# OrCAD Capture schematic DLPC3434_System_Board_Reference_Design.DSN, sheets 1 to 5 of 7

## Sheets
1 P07: Disclaimer
2 P01: Title Page: rev: A
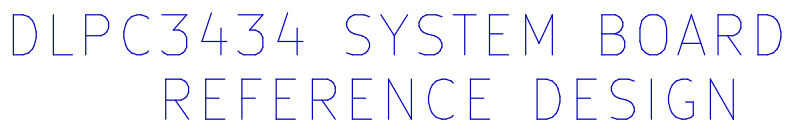
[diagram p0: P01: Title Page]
3 P06: Power Supplies: size D
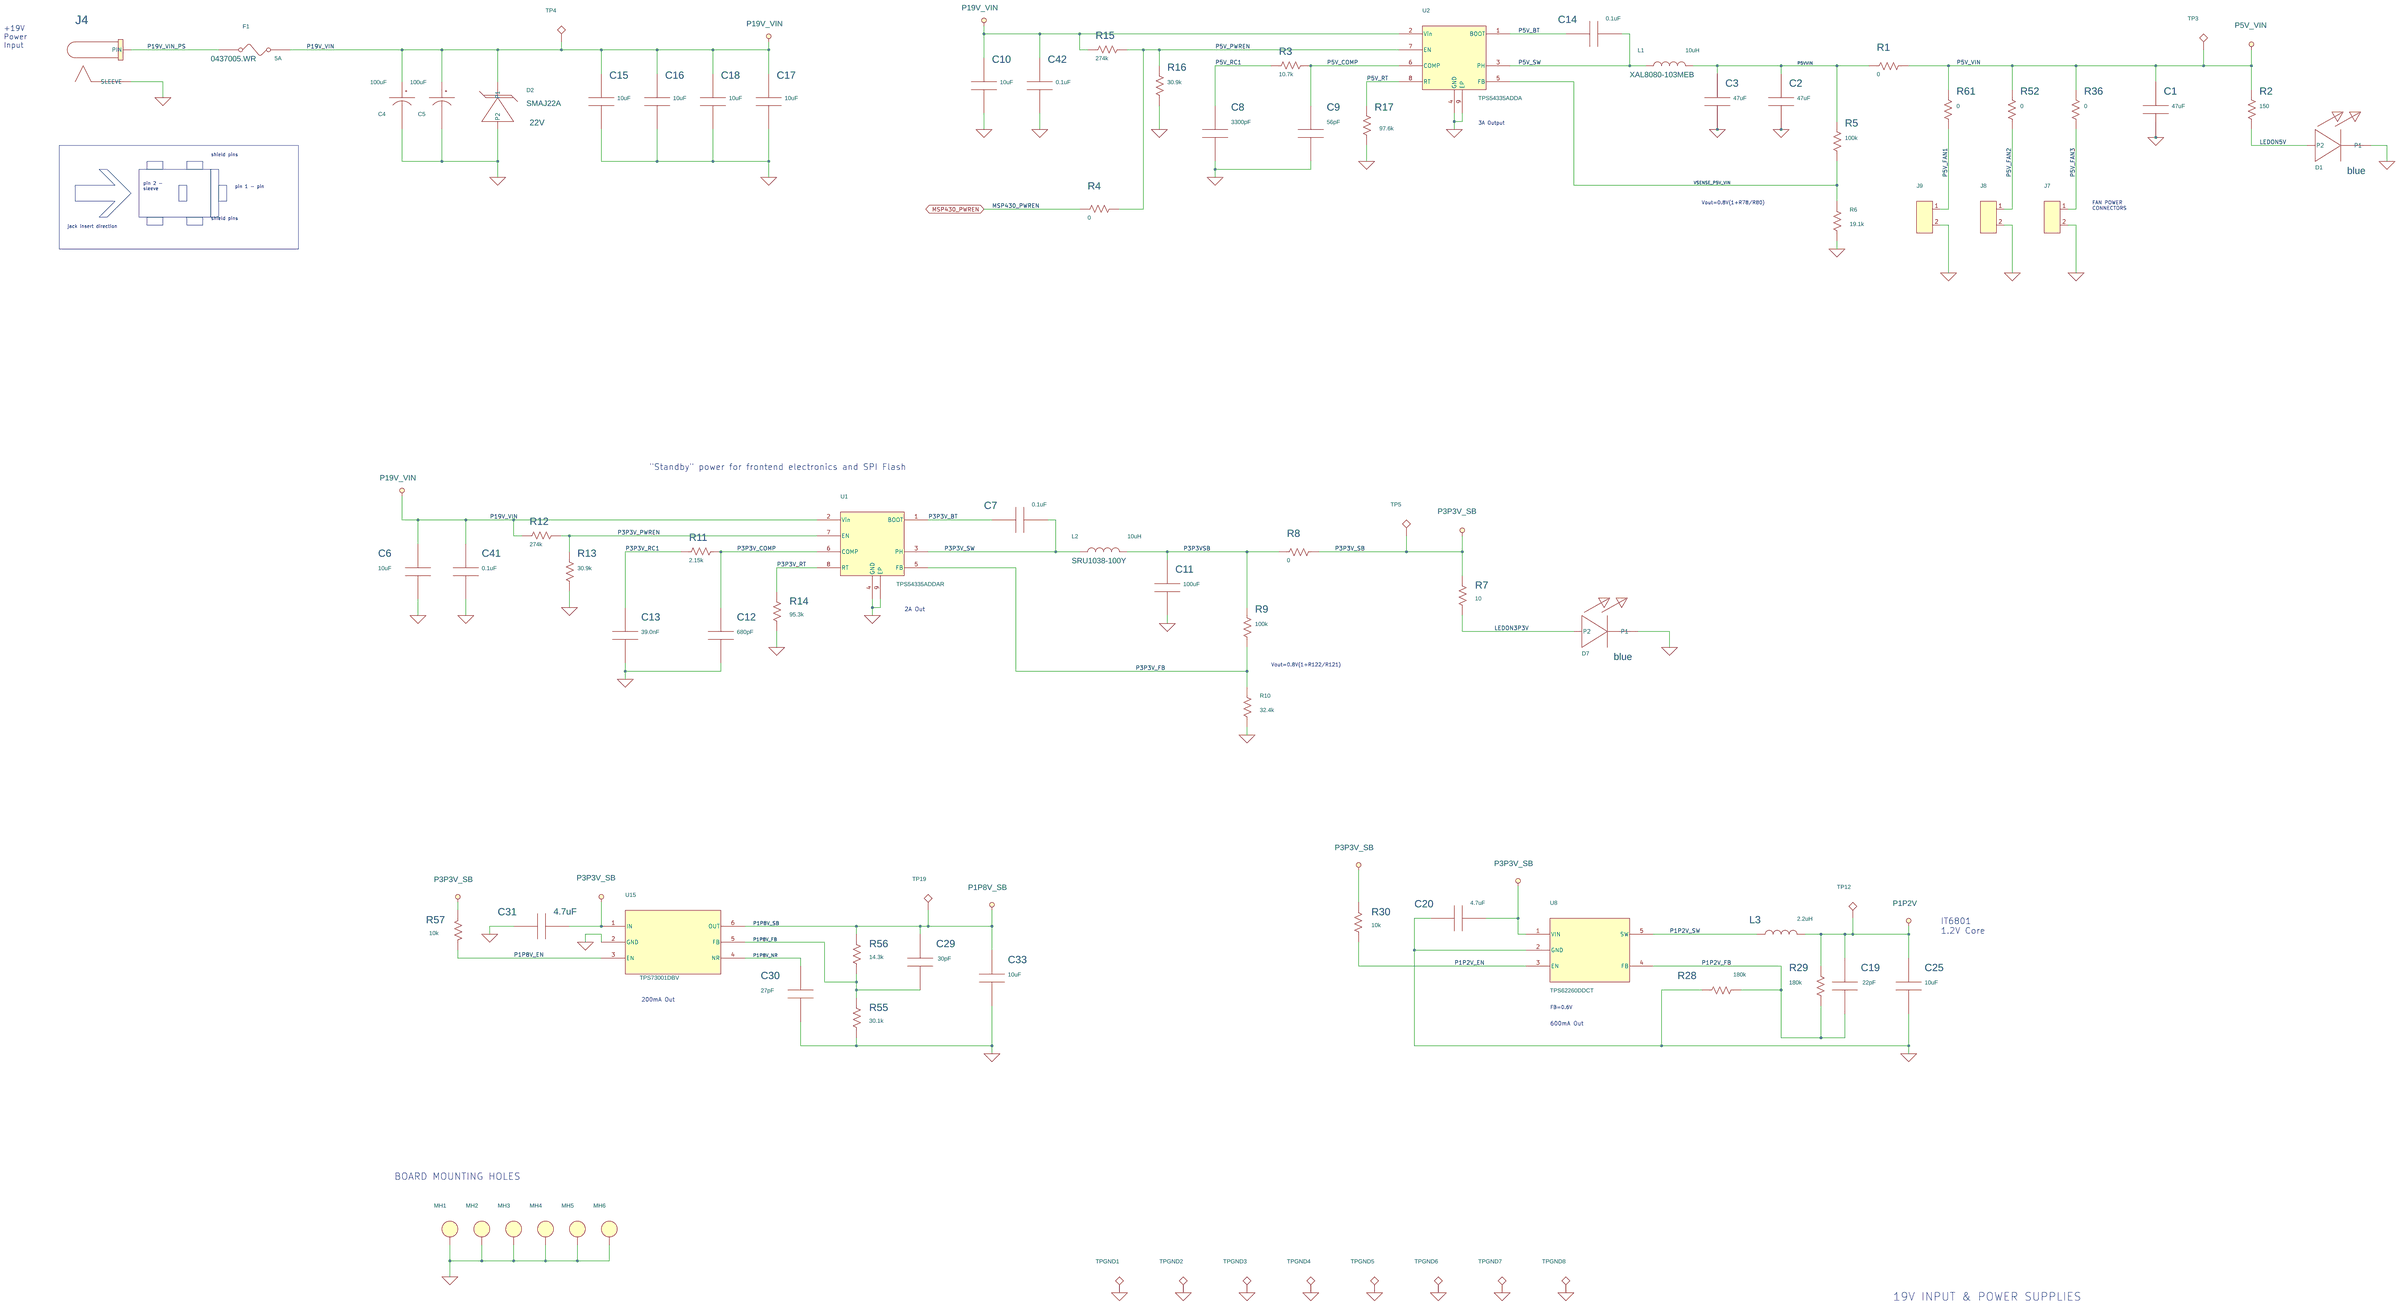
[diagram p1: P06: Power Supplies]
4 P03: IT6801 & HDMI: size D
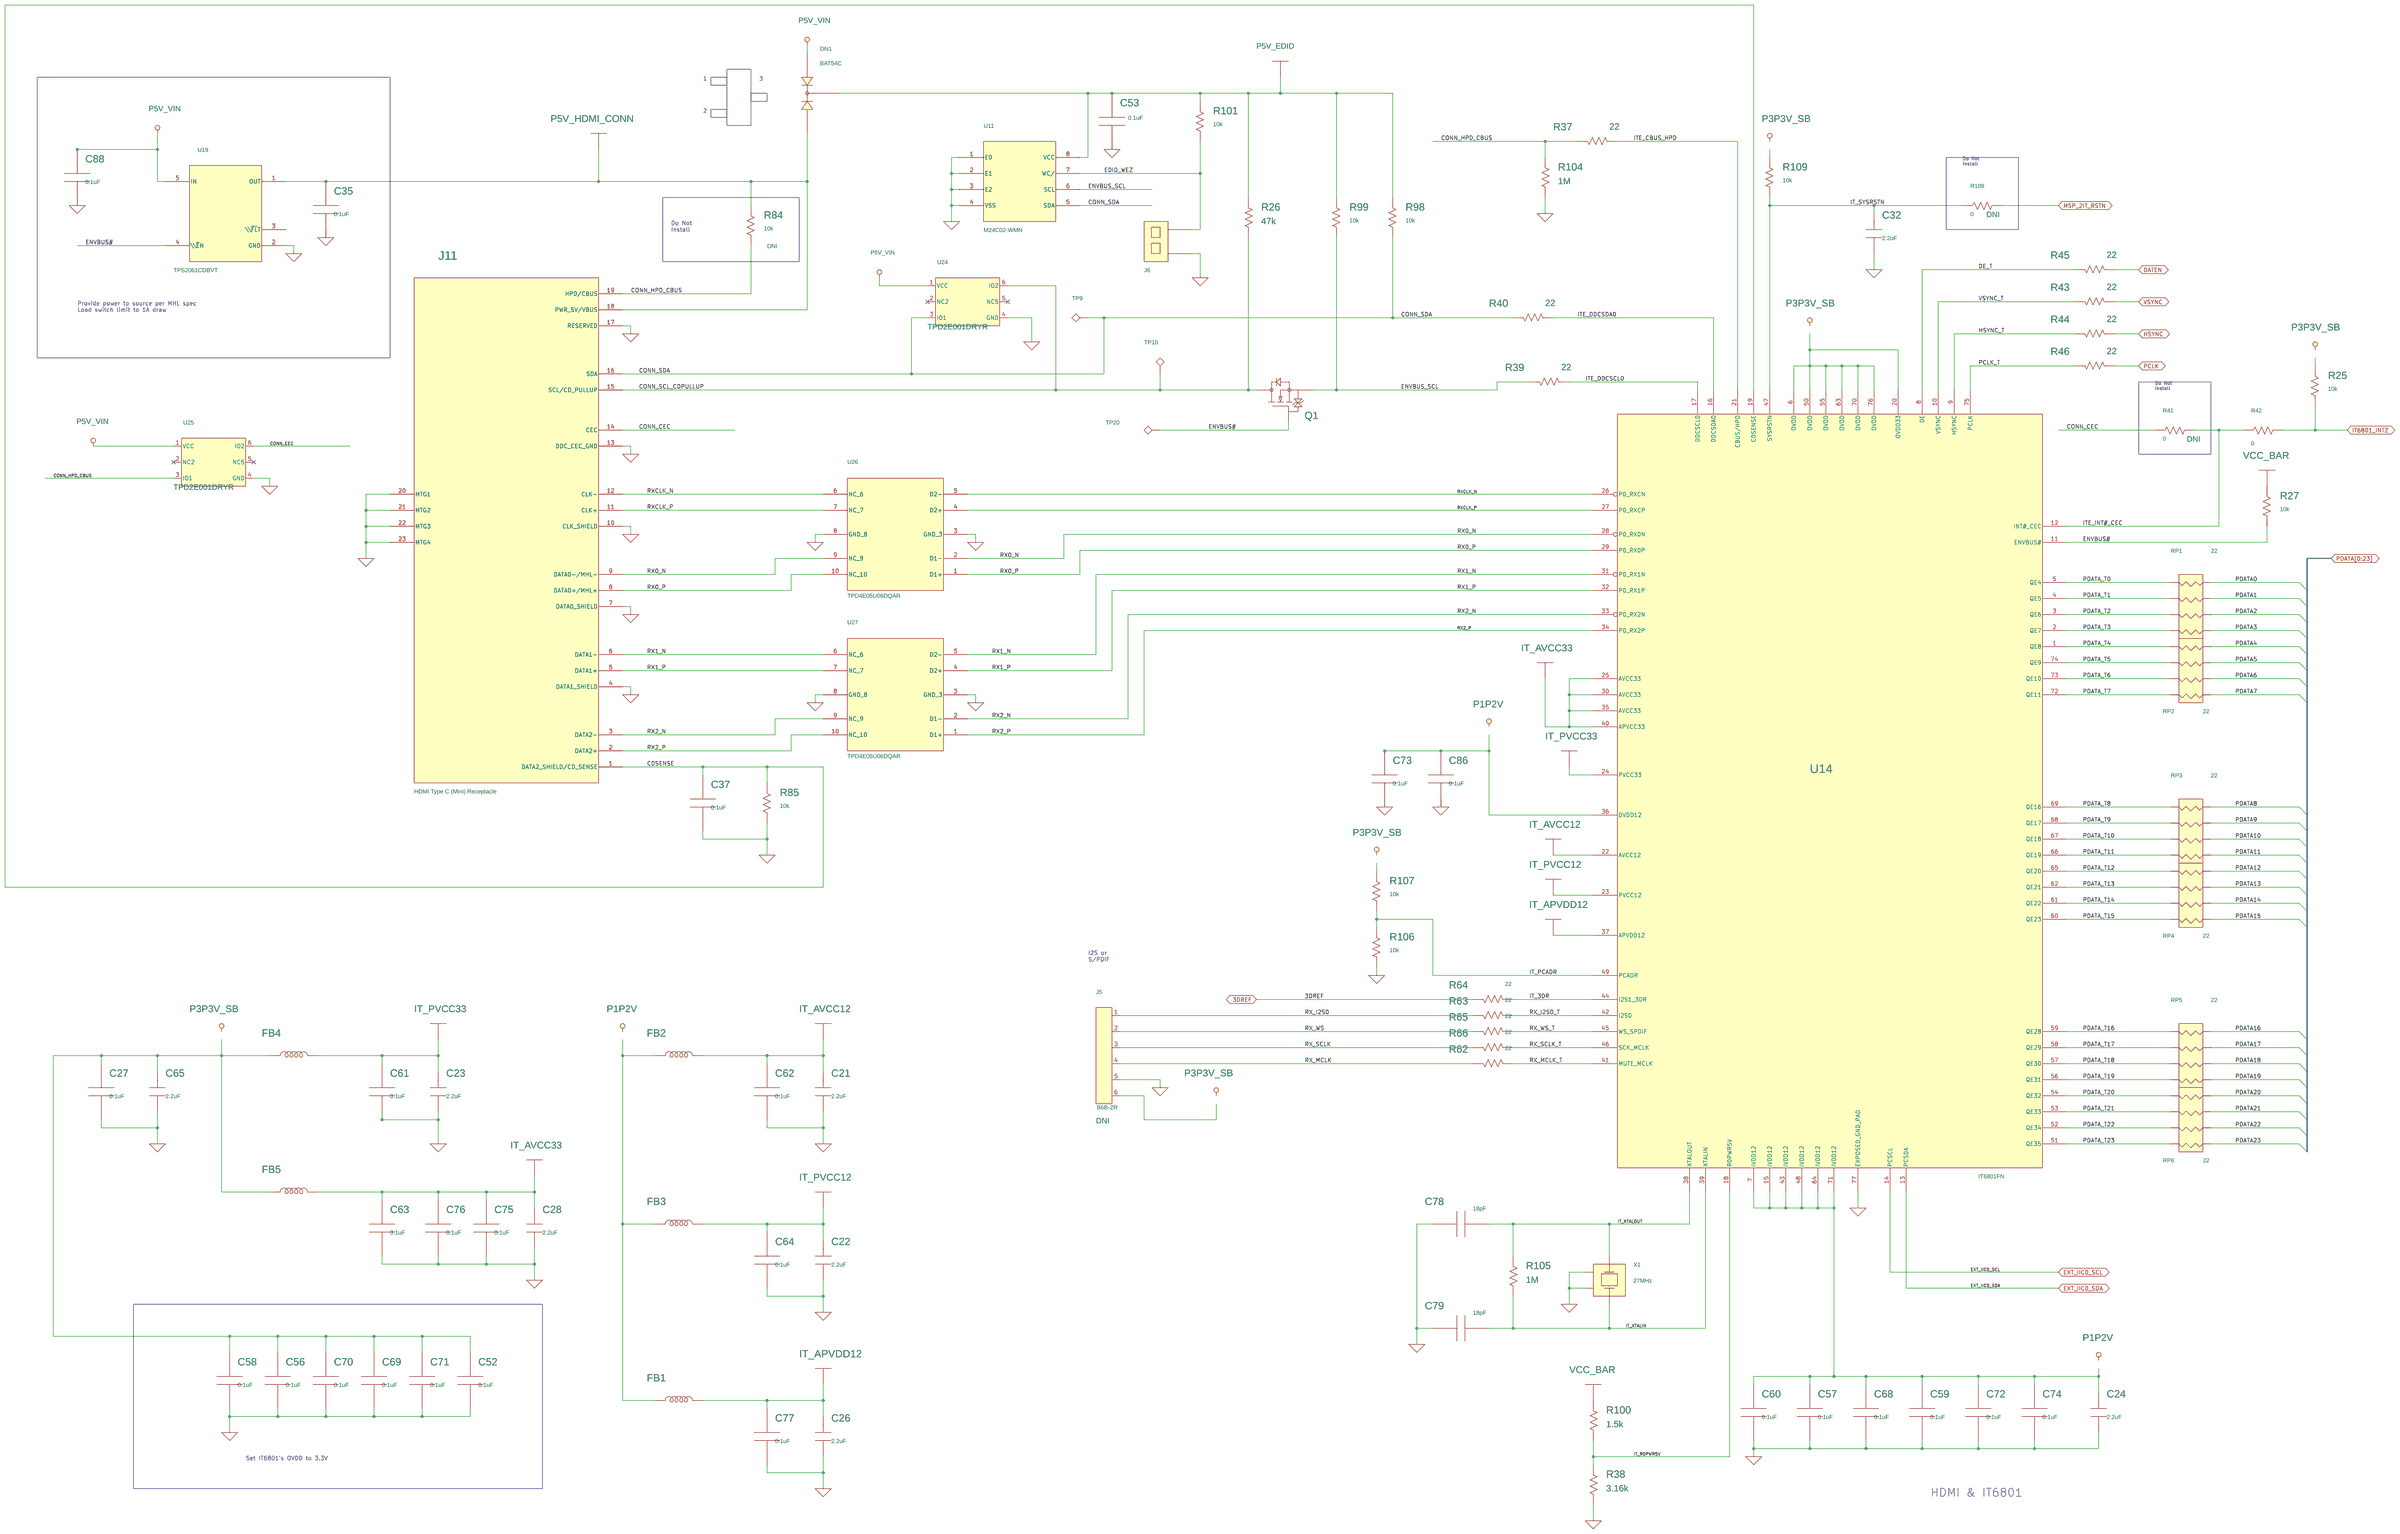
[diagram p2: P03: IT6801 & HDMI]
5 P05: I2C & USB Connections: size D
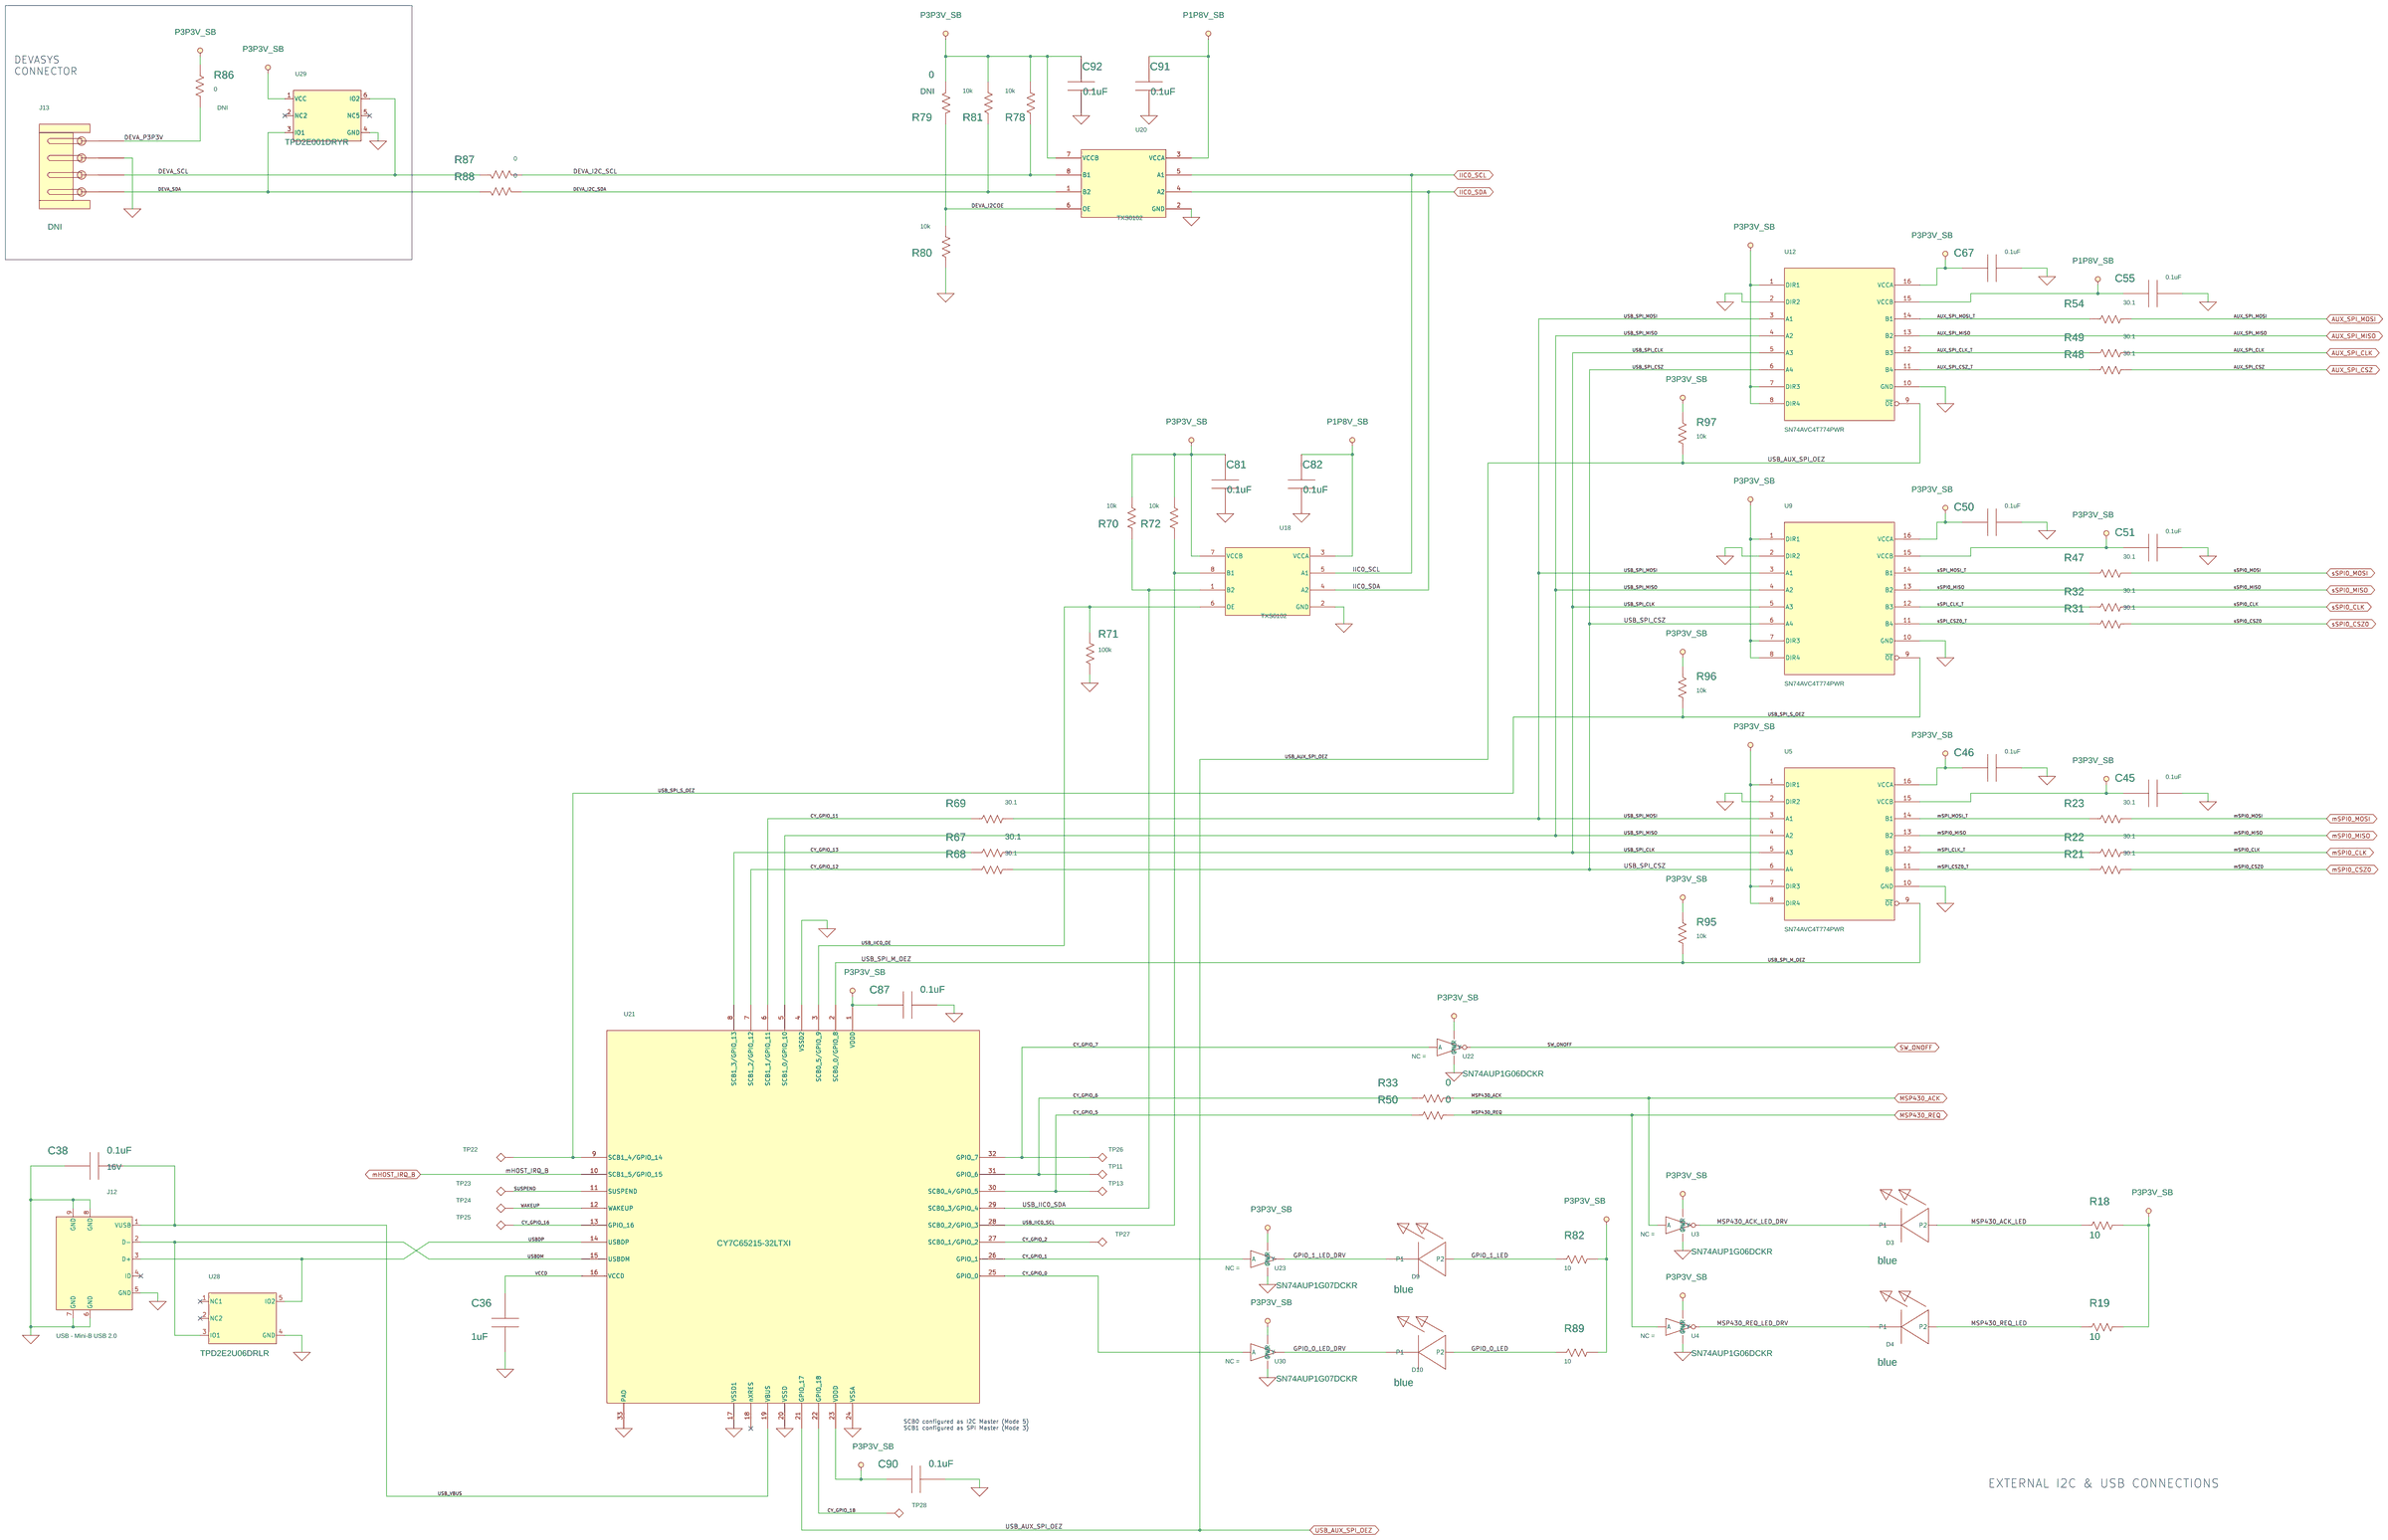
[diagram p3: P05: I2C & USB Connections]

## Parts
sheet P03: IT6801 & HDMI
C21  2.2uF  [0603]
C22  2.2uF  [0603]
C23  2.2uF  [0603]
C24  2.2uF  [0603]
C26  2.2uF  [0603]
C27  0.1uF  [0402]
C28  2.2uF  [0603]
C32  2.2uF  [0603]
C35  0.1uF  [0402]
C37  0.1uF  [0402]
C52  0.1uF  [0402]
C53  0.1uF  [0402]
C56  0.1uF  [0402]
C57  0.1uF  [0402]
C58  0.1uF  [0402]
C59  0.1uF  [0402]
C60  0.1uF  [0402]
C61  0.1uF  [0402]
C62  0.1uF  [0402]
C63  0.1uF  [0402]
C64  0.1uF  [0402]
C65  2.2uF  [0603]
C68  0.1uF  [0402]
C69  0.1uF  [0402]
C70  0.1uF  [0402]
C71  0.1uF  [0402]
C72  0.1uF  [0402]
C73  0.1uF  [0402]
C74  0.1uF  [0402]
C75  0.1uF  [0402]
C76  0.1uF  [0402]
C77  0.1uF  [0402]
C78  18pF  [0402]
C79  18pF  [0402]
C86  0.1uF  [0402]
C88  0.1uF  [0402]
DN1  BAT54C  [SOT-23-3]
FB1  BKP1005EM121-T  [0402]
FB2  BKP1005EM121-T  [0402]
FB3  BKP1005EM121-T  [0402]
FB4  BKP1005EM121-T  [0402]
FB5  BKP1005EM121-T  [0402]
J5  B6B-ZR  [JST_B6B-ZR-SM4-TF_LF_SN_P]
J6  M20-9990245  [HDR2P_1R]
J11  HDMI Type C (Mini) Receptacle  [CNC-2001-1-2-21-00-BK]
Q1  DMN26D0UT-7  [SOT_523]
R25  10k  [0402]
R26  47k  [0402]
R27  10k  [0402]
R37  22  [0402]
R38  3.16k  [0603]
R39  22  [0402]
R40  22  [0402]
R41  0  [0402]
R42  0  [0402]
R43  22  [0402]
R44  22  [0402]
R45  22  [0402]
R46  22  [0402]
R62  22  [0402]
R63  22  [0402]
R64  22  [0402]
R65  22  [0402]
R66  22  [0402]
R84  10k  [0402]
R85  10k  [0402]
R98  10k  [0402]
R99  10k  [0402]
R100  1.5k  [0402]
R101  10k  [0402]
R104  1M  [0402]
R105  1M  [0402]
R106  10k  [0402]
R107  10k  [0402]
R108  0  [0402]
R109  10k  [0402]
RP1  22  [0804]
RP2  22  [0804]
RP3  22  [0804]
RP4  22  [0804]
RP5  22  [0804]
RP6  22  [0804]
TP9  TP,40mil Drill,60mil Pad  [HOLE_PLATED_40mil_DRILL_60mil_PAD]
TP10  TP,40mil Drill,60mil Pad  [HOLE_PLATED_40mil_DRILL_60mil_PAD]
TP20  TP,12mil Drill,32mil Pad  [HOLE_PLATED_12mil_DRILL_32mil_PAD]
U11  M24C02-WMN  [SO8]
U14  IT6801FN  [ITE6801_76pin_QFN]
U19  TPS2061CDBVT  [SOT-753]
U24  TPD2E001DRY  [U_6_DRY]
U25  TPD2E001DRY  [U_6_DRY]
U26  TPD4E05U06DQAR  [10-UFDFN]
U27  TPD4E05U06DQAR  [10-UFDFN]
X1  27MHz  [4SMD]
sheet P05: I2C & USB Connections
C36  1uF  [0402]
C38  0.1uF  [0402_AVXA]
C45  0.1uF  [0402_AVXA]
C46  0.1uF  [0402_AVXA]
C50  0.1uF  [0402_AVXA]
C51  0.1uF  [0402_AVXA]
C55  0.1uF  [0402_AVXA]
C67  0.1uF  [0402_AVXA]
C81  0.1uF  [0402_AVXA]
C82  0.1uF  [0402_AVXA]
C87  0.1uF  [0402_AVXA]
C90  0.1uF  [0402_AVXA]
C91  0.1uF  [0402_AVXA]
C92  0.1uF  [0402_AVXA]
D3  blue  [1206]
D4  blue  [1206]
D9  blue  [1206]
D10  blue  [1206]
J12  USB - Mini-B USB 2.0  [MOLEX_USB_CONN_0513870578]
J13  S4B-EH(LF)(SN)  [CONN4-S4B-EH_JST]
R18  10  [0402]
R19  10  [0402]
R21  30.1  [0402]
R22  30.1  [0402]
R23  30.1  [0402]
R31  30.1  [0402]
R32  30.1  [0402]
R33  0  [0402]
R47  30.1  [0402]
R48  30.1  [0402]
R49  30.1  [0402]
R50  0  [0402]
R54  30.1  [0402]
R67  30.1  [0402]
R68  30.1  [0402]
R69  30.1  [0402]
R70  10k  [0402]
R71  100k  [0402]
R72  10k  [0402]
R78  10k  [0402]
R79  0  [0402]
R80  10k  [0402]
R81  10k  [0402]
R82  10  [0402]
R86  0  [0402]
R87  0  [0402]
R88  0  [0402]
R89  10  [0402]
R95  10k  [0402]
R96  10k  [0402]
R97  10k  [0402]
TP11  TP40  [TP40]
TP13  TP40  [TP40]
TP22  TP40  [TP40]
TP23  TP,12mil Drill,32mil Pad  [HOLE_PLATED_12mil_DRILL_32mil_PAD]
TP24  TP,12mil Drill,32mil Pad  [HOLE_PLATED_12mil_DRILL_32mil_PAD]
TP25  TP,12mil Drill,32mil Pad  [HOLE_PLATED_12mil_DRILL_32mil_PAD]
TP26  TP40  [TP40]
TP27  TP,12mil Drill,32mil Pad  [HOLE_PLATED_12mil_DRILL_32mil_PAD]
TP28  TP,12mil Drill,32mil Pad  [HOLE_PLATED_12mil_DRILL_32mil_PAD]
U3  SN74AUP1G06DCK  [U_5_DCK]
U4  SN74AUP1G06DCK  [U_5_DCK]
U5  SN74AVC4T774PWR  [TSSOP16_PW]
U9  SN74AVC4T774PWR  [TSSOP16_PW]
U12  SN74AVC4T774PWR  [TSSOP16_PW]
U18  TXS0102  [VSSOP-8_DCU]
U20  TXS0102  [VSSOP-8_DCU]
U21  CY7C65215-32LTXI  [CY7C65215_32pin_QFN]
U22  SN74AUP1G06DCK  [U_5_DCK]
U23  SN74AUP1G07DCK  [U_5_DCK]
U28  TPD2E2U06DRL  [SOT-5_DRL_R-PDSO-N5]
U29  TPD2E001DRY  [U_6_DRY]
U30  SN74AUP1G07DCK  [U_5_DCK]
sheet P06: Power Supplies
C1  47uF  [1206]
C2  47uF  [1206]
C3  47uF  [1206]
C4  100uF  [sizeD_260x260mil_radial_can]
C5  100uF  [sizeD_260x260mil_radial_can]
C6  10uF  [1206]
C7  0.1uF  [0402]
C8  3300pF  [0805]
C9  56pF  [0805]
C10  10uF  [1206]
C11  100uF  [1206]
C12  680pF  [0805]
C13  39.0nF  [0402]
C14  0.1uF  [0402]
C15  10uF  [1206]
C16  10uF  [1206]
C17  10uF  [1206]
C18  10uF  [1206]
C19  22pF  [0402]
C20  4.7uF  [0402]
C25  10uF  [0603]
C29  30pF  [0402]
C30  27pF  [0402]
C31  4.7uF  [0402]
C33  10uF  [0603]
C41  0.1uF  [0402]
C42  0.1uF  [0402]
D1  blue  [1206]
D2  SMAJ22A  [SMA]
D7  blue  [1206]
F1  5A  [1206]
J4  PJ-082BH  [CUI_PJ-082BH]
J7  S2B-ZR  [JST_S2B_ZR]
J8  S2B-ZR  [JST_S2B_ZR]
J9  S2B-ZR  [JST_S2B_ZR]
L1  10uH  [Coilcraft_XAL8080]
L2  10uH  [Bourns_SRU1038]
L3  2.2uH  [1008_2p5mmx2mm]
MH1  MOUNTING_HOLE  [MH147-276GND]
MH2  MOUNTING_HOLE  [MH147-276GND]
MH3  MOUNTING_HOLE  [MH147-276GND]
MH4  MOUNTING_HOLE  [MH147-276GND]
MH5  MOUNTING_HOLE  [MH147-276GND]
MH6  MOUNTING_HOLE  [MH147-276GND]
R1  0  [0805]
R2  150  [0402]
R3  10.7k  [0402]
R4  0  [0402]
R5  100k  [0402]
R6  19.1k  [0805]
R7  10  [0402]
R8  0  [0805]
R9  100k  [0402]
R10  32.4k  [0805]
R11  2.15k  [0402]
R12  274k  [0402]
R13  30.9k  [0402]
R14  95.3k  [0402]
R15  274k  [0402]
R16  30.9k  [0402]
R17  97.6k  [0402]
R28  180k  [0402]
R29  180k  [0402]
R30  10k  [0402]
R36  0  [0402]
R52  0  [0402]
R55  30.1k  [0402]
R56  14.3k  [0402]
R57  10k  [0402]
R61  0  [0402]
TP3  TP,40mil Drill,60mil Pad  [HOLE_PLATED_40mil_DRILL_60mil_PAD]
TP4  TP,40mil Drill,60mil Pad  [HOLE_PLATED_40mil_DRILL_60mil_PAD]
TP5  TP,40mil Drill,60mil Pad  [HOLE_PLATED_40mil_DRILL_60mil_PAD]
TP12  TP,40mil Drill,60mil Pad  [HOLE_PLATED_40mil_DRILL_60mil_PAD]
TP19  TP,40mil Drill,60mil Pad  [HOLE_PLATED_40mil_DRILL_60mil_PAD]
TPGND1  TP_BLK  [KEYSTONE_TP_MINIATURE]
TPGND2  TP_BLK  [KEYSTONE_TP_MINIATURE]
TPGND3  TP_BLK  [KEYSTONE_TP_MINIATURE]
TPGND4  TP_BLK  [KEYSTONE_TP_MINIATURE]
TPGND5  TP_BLK  [KEYSTONE_TP_MINIATURE]
TPGND6  TP_BLK  [KEYSTONE_TP_MINIATURE]
TPGND7  TP_BLK  [KEYSTONE_TP_MINIATURE]
TPGND8  TP_BLK  [KEYSTONE_TP_MINIATURE]
U1  TPS54335ADDAR  [8-SO-PWRPAD_DDA_R-PDSO-G8]
U2  TPS54335ADDA  [8-SO-PWRPAD_DDA_R-PDSO-G8]
U8  TPS62260DDCT  [TSOT-23_DDC_R-PDSO-G5]
U15  TPS73001DBV  [SOT23-6_DBV_R-PDSO-G6]

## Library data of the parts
C21-C24 C26 C28 C32 C65 = CER_2.2UF_25V_10%_X5R_0603: DigiKey: 587-2909-1-ND; DigiReel: 587-2909-6-ND; Install: Y; P/D_NUM: TMK107ABJ225KA-T; Part Number: TMK107ABJ225KA-T; Part Specific: 2.2µF 25V Ceramic Capacitor X5R 0603; Type: Capacitor; VPC: 25V; Vendor: Taiyo Yuden
C7 C14 C27 C35 C37 C41 C42 C52 C53 C56-C64 C68-C77 C86 C88 = PAS,CAP,NP,large: DigiKey: 445-6899-1-ND; DigiReel: 445-6899-6-ND; Family: passive; Lead Style: SMT; MFG: TDK; Material: X7R; P/D_NUM: CGA2B3X7R1H104K050BB; Part Number: CGA2B3X7R1H104K050BB; Part Specific: 0.10µF 50V Ceramic Capacitor X7R 0402; TOLERANCE: 10%; Type: capacitor; VENDOR: TDK; VPC: 50V
C78 C79 = PAS,CAP,NP,large: DigiKey: 490-5858-1-ND; DigiReel: 490-5858-6-ND; Family: passive; Lead Style: SMT; MFG: Murata; Material: NP0; P/D_NUM: GRM1555C1H180JA01D; Part Number: GRM1555C1H180JA01D; Part Specific: CAP CER 18PF 50V NP0 5% 0402; TOLERANCE: 5%; Type: capacitor; VENDOR: Murata; VPC: 50V
DN1 = DIODE_DUAL_Schott_Common_Cath: DigiKey: BAT54C-FDICT-ND; DigiReel: BAT54C-FDIDKR-ND; Install: Y; Lead Style: SMT; P/D_NUM: BAT54C-7-F; Part Number: BAT54C-7-F; Part Specific: DIODE ARRAY SCHOTTKY 30V 200mA SOT23-3; Type: Diode; VPC: 30V; Vendor: Diodes Inc.
FB1-FB5 = FERRITE_CHIP_120_OHM_1.5A_0402: DigiKey: 587-3289-1-ND; DigiReel: 587-3289-6-ND; Install: Y; Lead Style: SMT; Part Specific: FERRITE CHIP 80 OHM 1500MA 0402; Type: Ferrite; Vendor: Taiyo Yuden
J5 = EM,HDR,6P,1R,2x: DigiKey: 455-1685-1-ND; DigiReel: 455-1685-6-ND; Family: electro/mechanical; Install: DNI; Lead Style: SMT; MFG: JST; P/D_NUM: B6B-ZR-SM4-TF(LF)(SN)(P); Part Number: B6B-ZR-SM4-TF(LF)(SN)(P); Part Specific: CONN HEADER ZH TOP 6POS 1.5MM; Pin Cnt: 6; Pin Spacing: 1.5mm; Row Cnt: 1; Type: header; Vendor: JST
J6 = 2POS_SMT_HEADER_2_0.54MM: DigiKey: 952-2261-ND; DigiReel: ---; Digikey Part Number: 952-2261-ND; Family: electro/mechanical; Install: Y; Lead Style: TH; Part Specific: CONN HEADER 2 POS 0.1IN SIL VERT; Pin Cnt: 2; Pin Spacing: 100mil; Row Cnt: 1; Type: Header; Vendor: Harwin
J11 = HDMI-Mini_Receptacle_w_MHL: DigiKey: 1175-1704-1-ND; DigiReel: 1175-1704-6-ND; Digikey Part Number: 1175-1704-1-ND; Install: Y; Lead Style: SMT; MFG: CNC Tech; MFG Part Number: 2001-1-2-21-00-BK; P/D_NUM: 2001-1-2-21-00-BK; Part Number: 2001-1-2-21-00-BK; Part Specific: MINI HDMI 19P FEMALE SMT; Pin Cnt: 19; Pin Spacing: 0.4MM; Row Cnt: 1; Type: HDMI - Mini; Vendor: CNC Tech
Q1 = TMP_134732: DigiKey: DMN26D0UT-7DICT-ND; DigiReel: DMN26D0UT-7DIDKR-ND; Part Specific: MOSFET N-CH 20V 230MA SOT523; Type: Mosfet; VPC: 20V; Vendor: Diodes Inc
R25 R27 R30 R57 R70 R72 R78 R81 R85 R95-R99 R101 R106 R107 R109 = PAS,R,large: DigiKey: P10.0KLCT-ND; DigiReel: P10.0KLDKR-ND; Family: passive; Index PN: 680; Lead Style: SMT; MFG: Panasonic; Material: chip; P/D_NUM: ERJ-2RKF1002X; Part Number: ERJ-2RKF1002X; Part Specific: RES SMD 10K OHM 1% 1/10W 0402; Power: 1/16W; TOLERANCE: 1%; Type: resistor; VENDOR: Panasonic; VPC: 1/16W
R26 = PAS,R,large: DigiKey: P47.0KLCT-ND; DigiReel: P47.0KLDKR-ND; Family: passive; Index PN: 1030; Lead Style: SMT; MFG: Panasonic; Material: chip; P/D_NUM: ERJ-2RKF4702X; Part Number: ERJ-2RKF4702X; Part Specific: RES 47.0K OHM 1/10W 1% 0402 SMD; Type: resistor; VPC: 1/16W; Vendor: Panasonic
R37 R39 R40 R43-R46 R62-R66 = PAS,R,large: DigiKey: P22.0LCT-ND; DigiReel: P22.0LDKR-ND; Digikey Part Number: P22.0LCT-ND; Family: passive; Lead Style: SMT; MFG: Panasonic; MFG Part Number: ERJ-2RKF22R0X; Material: chip; P/D_NUM: ERJ-2RKF22R0X; Part Number: ERJ-2RKF22R0X; Part Specific: RES SMD 22 OHM 1% 1/10W 0402; Power: 1/16W; Rating: 1/10W; TOLERANCE: 1%; Type: resistor; VPC: 1/10W; Vendor: Panasonic
R38 = PAS,R,large: DigiKey: P3.16KHCT-ND; DigiReel: P3.16KHDKR-ND; Family: passive; Lead Style: SMT; MFG: Panasonic; Material: chip; P/D_NUM: ERJ-3EKF3161V; Part Number: ERJ-3EKF3161V; Part Specific: RES SMD 3.16K OHM 1% 1/10W 0603; TOLERANCE: 1%; Type: resistor; VENDOR: Panasonic; VPC: 1/10W
R41 R79 R86 R108 = PAS,R,large: DigiKey: P0.0JCT-ND; DigiReel: P0.0JDKR-ND; Family: passive; Index PN: 687; Install: DNI; Lead Style: SMT; MFG: Panasonic; Material: chip; P/D_NUM: ERJ-2GE0R00X; Part Number: ERJ-2GE0R00X; Part Specific: RES 0.0 OHM 1/16W 0402 SMD; Power: 1/16W; Type: resistor; VPC: 1/16W; Vendor: Panasonic
R4 R36 R42 R52 R61 = PAS,R,large: DigiKey: P0.0JCT-ND; DigiReel: P0.0JDKR-ND; Family: passive; Index PN: 687; Install: Y; Lead Style: SMT; MFG: Panasonic; Material: chip; P/D_NUM: ERJ-2GE0R00X; Part Number: ERJ-2GE0R00X; Part Specific: RES 0.0 OHM 1/16W 0402 SMD; Power: 1/16W; Type: resistor; VPC: 1/16W; Vendor: Panasonic
R84 = PAS,R,large: DigiKey: P10.0KLCT-ND; DigiReel: P10.0KLDKR-ND; Family: passive; Index PN: 680; Install: DNI; Lead Style: SMT; MFG: Panasonic; Material: chip; P/D_NUM: ERJ-2RKF1002X; Part Number: ERJ-2RKF1002X; Part Specific: RES SMD 10K OHM 1% 1/10W 0402; Power: 1/16W; TOLERANCE: 1%; Type: resistor; VENDOR: Panasonic; VPC: 1/16W
R100 = PAS,R,large: DigiKey: P1.50KLCT-ND; DigiReel: P1.50KLDKR-ND; Family: passive; Index PN: 1117; Lead Style: SMT; MFG: Panasonic; Material: chip; P/D_NUM: ERJ-2RKF1501X; Part Number: ERJ-2RKF1501X; Part Specific: RES 1.50K OHM 1/10W 1% 0402 SMD; TOLERANCE: 1%; Type: resistor; VENDOR: Panasonic; VPC: 1/10W
R104 R105 = PAS,R,large: DigiKey: P1.00MLCT-ND; DigiReel: P1.00MLDKR-ND; Family: passive; Index PN: 1229; Lead Style: SMT; MFG: Panasonic; P/D_NUM: ERJ-2RKF1004X; Part Number: ERJ-2RKF1004X; Part Specific: RES 1M OHM 1/10W 1% 0402 SMD; TOLERANCE: 1%; Type: resistor; VENDOR: Panasonic; VPC: 1/10W
RP1-RP6 = 22_OHM_ARR_1_32W_5%_0804: DigiKey: Y10220CT-ND; DigiReel: Y10220DKR-ND; Install: Y; P/D_NUM: EXB-N8V220JX; Part Number: EXB-N8V220JX; Part Specific: RES ARRAY 4 RES 22 OHM 0804; Type: Resistor Array; Vendor: Panasonic
TP3-TP5 TP9 TP10 TP12 TP19 = BF,HOLE,PLATED,TESTPIN: DigiKey: ---; DigiReel: ---; Family: board feature; Index PN: 377; Install: DNI; Lead Style: TH; MFG: -- NOT A PART --; Type: hole,plated; Vendor: -- NOT A PART --
TP20 TP23-TP25 TP27 TP28 = EM,TERM,TESTPOINT: Family: board feature; Index PN: 122; Install: DNI; MFG: -- NOT A PART --; Type: hole,plated; Vendor: -- NOT A PART --
U11 = M24C08L_dsize: DigiKey: 497-8552-1-ND; DigiReel: 497-8552-6-ND; Install: Y; P/D_NUM: M24C02-WMN6TP; Part Number: M24C02-WMN6TP; Part Specific: IC EEPROM 2KBIT 400KHZ 8SO; Type: EEPROM; Vendor: STMicroelectronics
U14 = INF,VIDEO,IT6801: Part Specific: IC RCVR HDMI SINGLE PORT 76-QFN
U19 = CURRENT_LIMIT_1A_SWITCH_SOT23-5: DigiKey: 296-35522-1-ND; DigiReel: 296-39352-6-ND; Install: Y; Part Specific: IC PWR DIST SWITCH SGL SOT23-5; Vendor: Texas Instruments
U24 U25 U29 = TPD2E001DRY: DigiKey: 296-21884-1-ND; DigiReel: 296-21884-6-ND; Family: passive; Index PN: 1029; Install: Y; Lead Style: SMT; MFG: Texas Instruments; P/D_NUM: TPD2E001DRYR; Part Number: TPD2E001DRYR; Part Specific: IC ESD-PROT ARRAY 2CH 6-SON; Type: diode,tvs
U26 U27 = ESD_HDMI_1.4_DIODE_TPD4E05U06: DigiKey: 296-35765-1-ND; DigiReel: 296-35765-6-ND; Install: Y; Part Specific: TVS DIODE 5.5VWM 14VC 10SON; Type: TVS Diode; Vendor: Texas Instruments
X1 = CRYSTAL_27MHZ_18PF_SMD: DigiKey: CTX843CT-ND; DigiReel: CTX843DKR-ND; Install: Y; P/D_NUM: 403C35D27M00000; Part Number: 403C35D27M00000; Part Specific: CRYSTAL 27MHZ 18P ±30ppm 60 Ohm 4P CSMD; Type: Crystal; Vendor: CTS
C36 = PAS,CAP,NP,large: DigiKey: 490-12702-1-ND; DigiReel: 490-12702-6-ND; Family: passive; Lead Style: SMT; MFG: Murata; Material: x5r; P/D_NUM: GRM155R61A105ME01D; Part Number: GRM155R61A105ME01D; Part Specific: CAP CER 1.0UF 10V X5R 0402; TOLERANCE: 20%; Type: capacitor; VENDOR: Murata; VPC: 10V
C38 C45 C46 C50 C51 C55 C67 C81 C82 C87 C90-C92 = PAS,CAP,NP,large: DigiKey: 445-4952-1-ND; DigiReel: 445-4952-6-ND; Family: passive; Index PN: 681; Lead Style: SMT; MFG: TDK; Material: x7r; P/D_NUM: C1005X7R1C104K050BC; Part Number: C1005X7R1C104K050BC; Part Specific: CAP CER .1UF 16V X7R 0402; TOLERANCE: 10%; Type: capacitor; VENDOR: TDK; VPC: 16V
D1 D3 D4 D7 D9 D10 = PAS,DIODE,LED,large: DigiKey: 67-1701-1-ND; DigiReel: 67-1701-6-ND; Family: passive; Index PN: 1250; Install: Y; Lead Style: SMT; MFG: Lumex; P/D_NUM: SML-LX1206USBC-TR; Part Number: SML-LX1206USBC-TR; Part Specific: LED INGAN/SIC U-BLUE CLR 1206SMD; Type: diode,led; VENDOR: Lumex
J12 = CON5_1: DigiKey: WM5462CT-ND; DigiReel: WM5462DKR-ND; Family: electro/mechanical; Install: Y; Lead Style: SMT; MFG: Molex; P/D_NUM: 0513870578; Part Number: 0513870578; Part Specific: CONN RECEPT MINI-USB R/A 5POS SMD; Pin Cnt: 5; Type: USB - mini B; Vendor: Molex
J13 = EM,CONN,4P,EH,Devasys: DigiKey: 455-1627-ND; DigiReel: ---; Family: electro/mechanical; Index PN: 1005; Install: DNI; Lead Style: TH; MFG: JST; Part Specific: CONN HEADER EH SIDE 4POS 2.5MM; Type: connector
R7 R18 R19 R82 R89 = PAS,R,large: DigiKey: P10.0LCT-ND; DigiReel: P10.0LDKR-ND; Family: passive; Index PN: 1099; Lead Style: SMT; MFG: Panasonic; Material: chip; P/D_NUM: ERJ-2RKF10R0X; Part Number: ERJ-2RKF10R0X; Part Specific: RES 10.0 OHM 1/10W 1% 0402 SMD; TOLERANCE: 1%; Type: resistor; VENDOR: Panasonic; VPC: 1/10W
R21-R23 R31 R32 R47-R49 R54 R67-R69 = PAS,R,large: DigiKey: P30.1LCT-ND; DigiReel: P30.1LDKR-ND; Family: passive; Index PN: 976; Lead Style: SMT; MFG: Panasonic; Material: chip; P/D_NUM: ERJ-2RKF30R1X; Part Number: ERJ-2RKF30R1X; Part Specific: RES 30.1 OHM 1/16W 1% 0402 SMD; Power: 1/16W; TOLERANCE: 1%; Type: resistor; VPC: 1/16W; Vendor: Panasonic
R33 R50 R87 R88 = PAS,R,large: DigiKey: P0.0JCT-ND; DigiReel: P0.0JDKR-ND; Family: passive; Index PN: 687; Lead Style: SMT; MFG: Panasonic; Material: chip; P/D_NUM: ERJ-2GE0R00X; Part Number: ERJ-2GE0R00X; Part Specific: RES 0.0 OHM 1/16W 0402 SMD; Power: 1/16W; Type: resistor; VPC: 1/16W; Vendor: Panasonic
R5 R9 R71 = PAS,R,large: DigiKey: 541-100KLCT-ND; DigiReel: 541-100KLDKR-ND; Family: passive; Lead Style: SMT; MFG: Vishay Dale; P/D_NUM: CRCW0402100KFKED; Part Number: CRCW0402100KFKED; Part Specific: RES SMD 100K OHM 1% 1/16W 0402; TOLERANCE: 1%; Type: Resistor; VENDOR: Vishay Dale; VPC: 1/16W
R80 = PAS,R,large: DigiKey: P10.0KLCT-ND; DigiReel: P10.0KLDKR-ND; Family: passive; Index PN: 680; Install: Y; Lead Style: SMT; MFG: Panasonic; Material: chip; P/D_NUM: ERJ-2RKF1002X; Part Number: ERJ-2RKF1002X; Part Specific: RES SMD 10K OHM 1% 1/10W 0402; Power: 1/16W; TOLERANCE: 1%; Type: resistor; VPC: 1/16W; Vendor: Panasonic
TP11 TP13 TP22 TP26 = EM,TERM,TESTPOINT: DigiKey: ---; DigiReel: ---; Family: board feature; Index PN: 995; Install: DNI; MFG: -- NOT A PART --; Type: hole,plated; Vendor: -- NOT A PART --
U3 U4 U22 = TMP_153924: DigiKey: 296-17562-1-ND; DigiReel: 296-17562-6-ND; Family: logic; Index PN: 1026; Lead Style: SMT; MFG: Texas Instruments; P/D_NUM: SN74AUP1G06DCKR; Part Number: SN74AUP1G06DCKR; Part Specific: IC INVERTER SINGLE 1INPUT SC705, open drain; Type: buffer
U5 U9 U12 = LOG,XCVR,74x4T774: DigiKey: 296-24739-1-ND; DigiReel: 296-24739-6-ND; Family: logic; Index PN: 871; Lead Style: SMT; MFG: Texas Instruments; Part Specific: IC BUS TRANSCVR 4BIT DL 16TSSOP; Type: transceiver; Vendor: Texas Instruments
U18 U20 = TXS0102: DigiKey: 296-21931-1-ND; DigiReel: 296-21931-6-ND; Family: interface; Index PN: 877; Install: Y; Lead Style: SMT; MFG: Texas Instruments; P/D_NUM: TXS0102DCUR; Part Number: TXS0102DCUR; Part Specific: IC VOLT-LEVEL TRANSLATOR 8-US8; Type: driver; VENDOR: Texas Instruments
U21 = INF,USB2SERIAL,CY7C65215_3: DigiKey: CY7C65215-32LTXI-ND; DigiReel: ---; Family: interface; Index PN: 1217; Lead Style: SMT; MFG: Cypress; Part Specific: IC USB TO UART BRIDGE DUAL 32QFN; Type: usb; Vendor: Cypress
U23 U30 = TMP_153900: DigiKey: 296-18256-1-ND; DigiReel: 296-18256-6-ND; Family: logic; Index PN: 1027; Install: Y; Lead Style: SMT; MFG: Texas Instruments; P/D_NUM: SN74AUP1G07DCKR; Part Number: SN74AUP1G07DCKR; Part Specific: IC BUFF/DVR LOW PWR N-INV SC705, open drain; Type: buffer
U28 = PAS,DIODE,TVS,TPD2E2U06DRL: DigiKey: 296-38361-1-ND; DigiReel: 296-38361-6-ND; Family: passive; Index PN: 1340; Lead Style: SMT; MFG: Texas Instruments; P/D_NUM: TPD2E2U06DRLR; Part Number: TPD2E2U06DRLR; Part Specific: TVS DIODE 5.5VWM 12.4VC 5SOT; Type: diode,tvs
C1-C3 = PAS,CAP,NP,large: DigiKey: 587-1780-1-ND; DigiReel: 587-1780-6-ND; Family: passive; Lead Style: SMT; MFG: Taiyo Yuden; P/D_NUM: LMK316BJ476ML-T; Part Number: LMK316BJ476ML-T; Part Specific: CAP CER 47UF 10V X5R 1206; TOLERANCE: 20%; Type: capacitor; VENDOR: Taiyo Yuden; VPC: 10V
C4 C5 = PAS,CAP,POLARIZED,large: DigiKey: PCE5007CT-ND; DigiReel: PCE5007DKR-ND; Index PN: 1277; Lead Style: SMT; MFG: Panasonic; Material: aluminum; P/D_NUM: EEE-FT1E101AP; Part Number: EEE-FT1E101AP; Part Specific: CAP ALUM 100UF 25V 20% SMD; Tolerance: 20%; VPC: 25V; Vendor: Panasonic
C6 C10 C15-C18 = PAS,CAP,NP,large: DigiKey: 490-5524-1-ND; DigiReel: 490-5524-6-ND; Family: passive; Lead Style: SMT; MFG: Murata; P/D_NUM: GRM31CR6YA106KA12L; Part Number: GRM31CR6YA106KA12L; Part Specific: CAP CER 10UF 35V 10% X5R 1206 SMD; TOLERANCE: 10%; Type: capacitor; VENDOR: Murata; VPC: 35V
C8 = PAS,CAP,NP,large: DigiKey: 490-12749-1-ND; DigiReel: 490-12749-6-ND; Family: passive; Lead Style: SMT; MFG: Murata; Material: X7R; P/D_NUM: GRM216R71E332KA01D; Part Number: GRM216R71E332KA01D; Part Specific: 3300pF 25V Ceramic Capacitor X7R 0805; TOLERANCE: 10%; Type: capacitor; VENDOR: Murata; VPC: 25V
C9 = PAS,CAP,NP,large: DigiKey: 311-1108-1-ND; DigiReel: 311-1108-6-ND; Family: passive; Lead Style: SMT; MFG: Yageo; Material: NP0; P/D_NUM: CC0805JRNPO9BN560; Part Number: CC0805JRNPO9BN560; Part Specific: 56pF 50V Ceramic Capacitor C0G, NP0 0805; TOLERANCE: 5%; Type: capacitor; VENDOR: Yageo; VPC: 50V
C11 = PAS,CAP,NP,large: DigiKey: 311-1991-1-ND; DigiReel: 311-1991-6-ND; Family: passive; Lead Style: SMT; MFG: Yageo; P/D_NUM: CC1206MKX5R5BB107; Part Number: CC1206MKX5R5BB107; Part Specific: CAP CER 100UF 6.3V X5R 1206; TOLERANCE: 20%; Type: capacitor; VENDOR: Yageo; VPC: 6.3V
C12 = PAS,CAP,NP,large: DigiKey: 311-1126-1-ND; DigiReel: 311-1126-6-ND; Family: passive; Lead Style: SMT; MFG: Yageo; Material: X7R; P/D_NUM: CC0805KRX7R9BB681; Part Number: CC0805KRX7R9BB681; Part Specific: 680pF 50V Ceramic Capacitor X7R 0805; TOLERANCE: 10%; Type: capacitor; VENDOR: Yageo; VPC: 50V
C13 = PAS,CAP,NP,large: DigiKey: 490-8252-1-ND; DigiReel: 490-8252-6-ND; Family: passive; Lead Style: SMT; MFG: Murata; Material: X5R; P/D_NUM: GRM155R61A393KA01D; Part Number: GRM155R61A393KA01D; Part Specific: 0.039µF 10V Ceramic Capacitor X5R 0402; TOLERANCE: 10%; Type: capacitor; VENDOR: Murata; VPC: 10V
C19 = PAS,CAP,NP,large: DigiKey: 490-5868-1-ND; DigiReel: 490-5868-6-ND; Family: passive; Lead Style: SMT; MFG: Murata; Material: npo; P/D_NUM: GRM1555C1H220JA01D; Part Number: GRM1555C1H220JA01D; Part Specific: CAP CER 22PF 50V 5% NP0 0402; TOLERANCE: 5%; Type: capacitor; VENDOR: Murata; VPC: 50V
C20 C31 = PAS,CAP,NP,large: DigiKey: 445-7395-1-ND; DigiReel: 445-7395-6-ND; Family: passive; Index PN: 1073; Lead Style: SMT; MFG: TDK; Material: x5r; P/D_NUM: C1005X5R0J475M050BC; Part Number: C1005X5R0J475M050BC; Part Specific: CAP CER 4.7UF 6.3V 20% X5R 0402; Type: capacitor; VENDOR: TDK; VPC: 6.3V
C25 C33 = PAS,CAP,NP,large: DigiKey: 445-4112-1-ND; DigiReel: 445-4112-6-ND; Family: passive; Index PN: 906; Lead Style: SMT; MFG: TDK; Material: x5r; P/D_NUM: C1608X5R0J106M080AB; Part Number: C1608X5R0J106M080AB; Part Specific: CAP CERAMIC 10UF 6.3V X5R 0603; TOLERANCE: 20%; Type: capacitor; VENDOR: TDK; VPC: 6.3V
C29 = PAS,CAP,NP,large: DigiKey: 490-5935-1-ND; DigiReel: 490-5935-6-ND; Family: passive; Lead Style: SMT; MFG: Murata; Material: npo; P/D_NUM: GRM1555C1H300JA01D; Part Number: GRM1555C1H300JA01D; Part Specific: CAP CER 30PF 50V 5% NP0 0402; TOLERANCE: 5%; Type: capacitor; VENDOR: Murata; VPC: 50V
C30 = PAS,CAP,NP,large: DigiKey: 490-5869-1-ND; DigiReel: 490-5869-6-ND; Family: passive; Index PN: 1339; Lead Style: SMT; MFG: Murata; Material: npo; P/D_NUM: GRM1555C1H270JA01D; Part Number: GRM1555C1H270JA01D; Part Specific: CAP CER 27PF 50V 5% NP0 0402; TOLERANCE: 5%; Type: capacitor; VENDOR: Murata; VPC: 50V
D2 = PAS,DIODE,TVS,large: DigiKey: SMAJ22ABCT-ND; DigiReel: SMAJ22ABDKR-ND; Family: passive; Index PN: 1279; Lead Style: SMT; MFG: Bourns; Part Specific: TVS DIODE 22VWM SMD package DO214AC_SMA; Type: diode,tvs; VENDOR: Bourns; VPC: 22V; Voltage: 22V
F1 = FUSE_10A_125V_FAST_2410: FUSE BRD MNT 5A 32VAC 35VDC 1206; DigiKey: F2890CT-ND; DigiReel: F2890DKR-ND; Digikey Part Number: F2890CT-ND; Install: Y; MFG: LittleFuse; MFG Part Number: 0437005.WR; P/D_NUM: 0437005.WR; Part Number: 0437005.WR; Part Specific: FUSE BRD MNT 5A 32VAC 35VDC 1206; Type: Fuse; VPC: 35V; Vendor: LittleFuse
J4 = EM,CONN,PWRJACK,PJ-082BH: DigiKey: CP-082BHCT-ND; DigiReel: CP-082BHTR-ND; Lead Style: TH; Part Specific: CONN PWR JACK 2.5X5.5MM SOLDER; Pin Cnt: 2; Type: power jack; VENDOR: CUI Inc; VPC: 10A
J7-J9 = EM,CONN,2P,1R: DigiKey: 455-1669-ND; Family: electro/mechanical; Lead Style: TH; MFG: JST; P/D_NUM: S2B-ZR(LF)(SN); Part Number: S2B-ZR(LF)(SN); Part Specific: CONN HEADER ZH SIDE 2POS 1.5MM; Pin Cnt: 2; Pin Spacing: 1.5mm; Row Cnt: 1; Type: header; VENDOR: JST
L1 = PAS,INDUCTOR,_large: DigiKey: ---; DigiReel: ---; Family: passive; Lead Style: SMT; MFG: Coilcraft; P/D_NUM: XAL8080-103MEB; Part Number: XAL8080-103MEB; Part Specific: Inductor 10 uH 6 A 20% SMD; Type: inductor; VENDOR: Coilcraft; VPC: 8.7A
L2 = PAS,INDUCTOR,_large: DigiKey: SRU1038-100YCT-ND; DigiReel: SRU1038-100YDKR-ND; Family: passive; Lead Style: SMT; MFG: Bourns; P/D_NUM: SRU1038-100Y; Part Number: SRU1038-100Y; Part Specific: FIXED IND 10UH 3.8A 25 MOHM SMD; Type: inductor; VENDOR: Coilcraft; VPC: 3.8 A
L3 = PAS,INDUCTOR,_large: DigiKey: 490-5114-1-ND; DigiReel: 490-5114-6-ND; Family: passive; Index PN: 1149; Install: Y; Lead Style: SMT; MFG: Murata; P/D_NUM: LQM2HPN2R2MG0L; Part Number: LQM2HPN2R2MG0L; Part Specific: INDUCTOR 2.2UH 20% 1300MA 1008; Type: inductor; VENDOR: Murata
MH1-MH6 = MOUNTING_HOLE: Part Number: -- NOT A PART --; Part Specific: MOUNTING HOLE
R1 R8 = PAS,R,large: DigiKey: P0.0ACT-ND; DigiReel: P0.0ADKR-ND; Family: passive; Install: Y; Lead Style: SMT; MFG: Panasonic; Material: chip; P/D_NUM: ERJ-6GEY0R00V; Part Number: ERJ-6GEY0R00V; Part Specific: RES SMD 0.0 OHM JUMPER 1/8W 0805; Power: 1/8W; Type: resistor; VPC: 2A; Vendor: Panasonic
R2 = PAS,R,large: DigiKey: P150LCT-ND; DigiReel: P150LDKR-ND; Family: passive; Index PN: 707; Lead Style: SMT; MFG: Panasonic; Material: Chip; P/D_NUM: ERJ-2RKF1500X; Part Number: ERJ-2RKF1500X; Part Specific: RES 150 OHM 1/10W 1% 0402 SMD; TOLERANCE: 1%; Type: resistor; VENDOR: Panasonic; VPC: 1/10W
R3 = PAS,R,large: DigiKey: 541-10.7KLCT-ND; DigiReel: 541-10.7KLDKR-ND; Family: passive; MFG: Vishay Dale; Material: chip; P/D_NUM: CRCW040210K7FKED; Part Number: CRCW040210K7FKED; Part Specific: RES SMD 10.7K OHM 1% 1/16W 0402; Power: 1/16W; TOLERANCE: 1%; Type: resistor; VENDOR: Vishay Dale; VPC: 1/16W
R6 = PAS,R,large: DigiKey: P19.1KCCT-ND; DigiReel: P19.1KCDKR-ND; Family: passive; MFG: Panasonic; Material: chip; P/D_NUM: ERJ-6ENF1912V; Part Number: ERJ-6ENF1912V; Part Specific: RES SMD 19.1K OHM 1% 1/8W 0805; Power: 1/8W; TOLERANCE: 1%; Type: resistor; VENDOR: Panasonic; VPC: 1/8W
R10 = PAS,R,large: DigiKey: P32.4KCCT-ND; DigiReel: P32.4KCDKR-ND; Family: passive; MFG: Panasonic; Material: chip; P/D_NUM: ERJ-6ENF3242V; Part Number: ERJ-6ENF3242V; Part Specific: RES SMD 32.4K OHM 1% 1/8W 0805; Power: 1/8W; TOLERANCE: 1%; Type: resistor; VENDOR: Panasonic; VPC: 1/8W
R11 = PAS,R,large: DigiKey: 541-2.15KLCT-ND; DigiReel: 541-2.15KLDKR-ND; Family: passive; MFG: Vishay Dale; Material: chip; P/D_NUM: CRCW04022K15FKED; Part Number: CRCW04022K15FKED; Part Specific: RES SMD 2.15K OHM 1% 1/16W 0402; Power: 1/16W; TOLERANCE: 1%; Type: resistor; VENDOR: Vishay Dale; VPC: 1/16W
R12 R15 = PAS,R,large: DigiKey: 541-274KLCT-ND; DigiReel: 541-274KLDKR-ND; Family: passive; MFG: Vishay Dale; Material: chip; P/D_NUM: CRCW0402274KFKED; Part Number: CRCW0402274KFKED; Part Specific: RES SMD 274K OHM 1% 1/16W 0402; Power: 1/16W; TOLERANCE: 1%; Type: resistor; VENDOR: Vishay Dale; VPC: 1/16W
R13 R16 = PAS,R,large: DigiKey: 541-30.9KLCT-ND; DigiReel: 541-30.9KLDKR-ND; Family: passive; MFG: Vishay Dale; Material: chip; P/D_NUM: CRCW040230K9FKED; Part Number: CRCW040230K9FKED; Part Specific: RES SMD 30.9K OHM 1% 1/16W 0402; Power: 1/16W; TOLERANCE: 1%; Type: resistor; VENDOR: Vishay Dale; VPC: 1/16W
R14 = PAS,R,large: DigiKey: 541-95.3KLCT-ND; DigiReel: 541-95.3KLDKR-ND; Family: passive; MFG: Vishay Dale; Material: chip; P/D_NUM: CRCW040295K3FKED; Part Number: CRCW040295K3FKED; Part Specific: RES SMD 95.3K OHM 1% 1/16W 0402; Power: 1/16W; TOLERANCE: 1%; Type: resistor; VENDOR: Vishay Dale; VPC: 1/16W
R17 = PAS,R,large: DigiKey: 541-97.6KLCT-ND; DigiReel: 541-97.6KLDKR-ND; Family: passive; MFG: Vishay Dale; Material: chip; P/D_NUM: CRCW040297K6FKED; Part Number: CRCW040297K6FKED; Part Specific: RES SMD 97.6K OHM 1% 1/16W 0402; Power: 1/16W; TOLERANCE: 1%; Type: resistor; VENDOR: Vishay Dale; VPC: 1/16W
R28 R29 = PAS,R,large: DigiKey: 311-180KLRCT-ND; DigiReel: 311-180KLRDKR-ND; Family: passive; Index PN: 1179; Lead Style: SMT; MFG: Yageo; P/D_NUM: RC0402FR-07180KL; Part Number: RC0402FR-07180KL; Part Specific: RES 180K OHM 1/16W 1% 0402 SMD; TOLERANCE: 1%; Type: resistor; VENDOR: Yageo; VPC: 1/16W
R55 = PAS,R,large: DigiKey: P30.1KLCT-ND; DigiReel: P30.1KLDKR-ND; Family: passive; Index PN: 1335; Lead Style: SMT; MFG: Panasonic; P/D_NUM: ERJ-2RKF3012X; Part Number: ERJ-2RKF3012X; Part Specific: RES SMD 30.1K OHM 1% 1/10W 0402; TOLERANCE: 1%; Type: resistor; VENDOR: Panasonic; VPC: 1/16W
R56 = PAS,R,large: DigiKey: P14.3KLCT-ND; DigiReel: P14.3KLDKR-ND; Family: passive; Index PN: 1334; Lead Style: SMT; MFG: Panasonic; P/D_NUM: ERJ-2RKF1432X; Part Number: ERJ-2RKF1432X; Part Specific: RES SMD 14.3K OHM 1% 1/10W 0402; TOLERANCE: 1%; Type: resistor; VENDOR: Panasonic; VPC: 1/16W
TPGND1-TPGND8 = EM,TERM,TESTPOINT: DigiKey: 5001K-ND; DigiReel: ---; Family: electro/mechanical; Index PN: 946; Install: Y; Lead Style: TH; MFG: Keystone; P/D_NUM: 5001; Part Number: 5001; Part Specific: TEST POINT PC MINI .040inD BLACK; Type: terminal; Vendor: Keystone
U1 = RT8272_SOP8_7: DigiKey: 296-43617-1-ND; DigiReel: 296-43617-6-ND; Family: power; Index PN: 1342; Install: Y; Lead Style: SMT; MFG: Texas Instruments; Part Specific: IC REG BCK ADJ 3A SYNC 8SOPWRPAD; Type: reg,switching; Vendor: Texas Instruments
U2 = RT8272_SOP8_7: DigiKey: 296-43617-1-ND; DigiReel: 296-43617-6-ND; Family: power; Index PN: 1342; Install: Y; Lead Style: SMT; MFG: Texas Instruments; P/D_NUM: TPS54335ADDAR; Part Number: TPS54335ADDAR; Part Specific: IC REG BCK ADJ 3A SYNC 8SOPWRPAD; Type: reg,switching; Vendor: Texas Instruments
U8 = PWR,REG,TPS62260,TSOT23_DDC: DigiKey: 296-22469-1-ND; DigiReel: 296-22469-6-ND; Family: power; Index PN: 1147; Install: Y; Lead Style: SMT; MFG: Texas Instruments; Part Specific: IC REG BUCK SYNC ADJ TSOT23-5; Type: regulator; Vendor: Texas Instruments
U15 = PWR,REG,TPS73001: DigiKey: 296-27055-1-ND; DigiReel: 296-27055-6-ND; Family: power; Index PN: 1331; Lead Style: SMT; MFG: Texas Instruments; P/D_NUM: TPS73001DBVR; Part Number: TPS73001DBVR; Part Specific: IC REG LDO ADJ 0.2A SOT23-5; Type: reg,ldo; Vendor: Texas Instruments

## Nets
DGND: C1.2(N) C2.2(N) C3.2(N) C4.2(N) C5.2(N) C6.2(N) C8.1(P) C9.1(P) C10.2(N) C11.2(N) C12.1(P) C13.1(P) C15.2(N) C16.2(N) C17.2(N) C18.2(N) C20.1(P) C21.2 C22.2 C23.2 C24.2 C25.2(N) C26.2 C27.2(N) C28.2 C30.2(N) C31.1(P) C32.2 C33.2(N) C35.2(N) C36.2(N) C37.2(N) C38.1(P) C41.1(P) C42.1(P) C45.2(N) C46.2(N) C50.2(N) C51.2(N) C52.2(N) C53.2(N) C55.2(N) C56.2(N) C57.2(N) C58.2(N) C59.2(N) C60.2(N) C61.2(N) C62.2(N) C63.2(N) C64.2(N) C65.2 C67.2(N) C68.2(N) C69.2(N) C70.2(N) C71.2(N) C72.2(N) C73.2(N) C74.2(N) C75.2(N) C76.2(N) C77.2(N) C78.2(N) C79.2(N) C81.2(N) C82.2(N) C86.2(N) C87.2(N) C88.2(N) C90.2(N) C91.2(N) C92.2(N) D1.1(P1) D2.2(P2) D7.1(P1) J4.2(SLEEVE) J5.5 J6.2 J7.2 J8.2 J9.2 J11.4(DATA1_SHIELD) J11.7(DATA0_SHIELD) J11.10(CLK_SHIELD) J11.13(DDC_CEC_GND) J11.17(RESERVED) J11.20(MTG1) J11.21(MTG2) J11.22(MTG3) J11.23(MTG4) J12.5(GND) J12.6(GND) J12.7(GND) J12.8(GND) J12.9(GND) J13.3 MH1.1 MH2.1 MH3.1 MH4.1 MH5.1 MH6.1 R6.2(N2) R10.2(N2) R13.2(N2) R14.2(N2) R16.2(N2) R17.2(N2) R28.2(N2) R38.2(N2) R55.2(N2) R71.2(N2) R80.2(N2) R85.1(N1) R104.2(N2) R106.1(N1) TPGND1.1(P1) TPGND2.1(P1) TPGND3.1(P1) TPGND4.1(P1) TPGND5.1(P1) TPGND6.1(P1) TPGND7.1(P1) TPGND8.1(P1) U1.4(GND) U1.9(EP) U2.4(GND) U2.9(EP) U3.3(GND) U4.3(GND) U5.2(DIR2) U5.10(GND) U8.2(GND) U9.2(DIR2) U9.10(GND) U11.1(E0) U11.2(E1) U11.3(E2) U11.4(VSS) U12.2(DIR2) U12.10(GND) U14.77(EXPOSED_GND_PAD) U15.2(GND) U18.2(GND) U19.2(GND) U20.2(GND) U21.4(VSSD2) U21.17(VSSD1) U21.20(VSSD) U21.24(VSSA) U21.33(PAD) U22.3(GND) U23.3(GND) U24.4(GND) U25.4(GND) U26.3(GND) U26.8(GND) U27.3(GND) U27.8(GND) U28.4(GND) U29.4(GND) U30.3(GND) X1.2 X1.4 ; also on sheet 6 7
P5V_BT: C14.1(P) U2.1(BOOT)
P5V_COMP: C9.2(N) R3.2(N2) U2.6(COMP)
P5V_EDID: C53.1(P) DN1.3 R26.1(N1) R27.2(N2) R98.2(N2) R99.2(N2) R101.2(N2) U11.8(VCC)
P5V_FAN1: J9.1 R61.1(N1)
P5V_FAN2: J8.1 R52.1(N1)
P5V_FAN3: J7.1 R36.1(N1)
P5V_HDMI_CONN: C35.1(P) DN1.1 J11.18(PWR_5V/VBUS) R84.2(N2) R100.1(N1) U19.1(OUT)
P5V_PWREN: R4.2(N2) R15.2(N2) R16.1(N1) U2.7(EN)
P5V_RC1: C8.2(N) R3.1(N1)
P5V_RT: R17.1(N1) U2.8(RT)
P5V_SW: C14.2(N) L1.2 U2.3(PH)
P5V_VIN: C1.1(P) C88.1(P) DN1.2 R1.1(N1) R2.1(N1) R36.2(N2) R52.2(N2) R61.2(N2) TP3.1(P1) U19.5(IN) U24.1(VCC) U25.1(VCC) ; also on sheet 7
P5VVIN: C2.1(P) C3.1(P) L1.1 R1.2(N2) R5.1(N1)
P19V_VIN: C4.1(P) C5.1(P) C6.1(P) C10.1(P) C15.1(P) C16.1(P) C17.1(P) C18.1(P) C41.2(N) C42.2(N) D2.1(P1) F1.2 R12.1(N1) R15.1(N1) TP4.1(P1) U1.2(Vin) U2.2(Vin) ; also on sheet 7
P19V_VIN_PS: F1.1 J4.1(PIN)
VCCD: C36.1(P) U21.16(VCCD)
3DREF: R64.2(N2) ; also on sheet 7
AUX_SPI_CLK: R49.1(N1) ; also on sheet 7
AUX_SPI_CLK_T: R49.2(N2) U12.12(B3)
AUX_SPI_CSZ: R48.1(N1) ; also on sheet 7
AUX_SPI_CSZ_T: R48.2(N2) U12.11(B4)
AUX_SPI_MISO: U12.13(B2) ; also on sheet 7
AUX_SPI_MOSI: R54.1(N1) ; also on sheet 7
AUX_SPI_MOSI_T: R54.2(N2) U12.14(B1)
CDSENSE: C37.1(P) J11.1(DATA2_SHIELD/CD_SENSE) R85.2(N2) U14.19(CDSENSE)
CONN_CEC: J11.14(CEC) R41.2(N2) U25.6(IO2)
CONN_HPD_CBUS: J11.19(HPD/CBUS) R37.2(N2) R84.1(N1) R104.1(N1) U25.3(IO1)
CONN_SCL_CDPULLUP: J11.15(SCL/CD_PULLUP) Q1.3(D) R26.2(N2) TP10.1(P1) U24.6(IO2)
CONN_SDA: J11.16(SDA) R40.2(N2) R98.1(N1) TP9.1(P1) U11.5(SDA) U24.3(IO1)
CY_GPIO_0: U21.25(GPIO_0) U30.2(A)
CY_GPIO_1: U21.26(GPIO_1) U23.2(A)
CY_GPIO_2: TP27.1(P1) U21.27(SCB0_1/GPIO_2)
CY_GPIO_5: R50.2(N2) TP13.1(P1) U21.30(SCB0_4/GPIO_5)
CY_GPIO_6: R33.2(N2) TP11.1(P1) U21.31(GPIO_6)
CY_GPIO_7: TP26.1(P1) U21.32(GPIO_7) U22.2(A)
CY_GPIO_11: R69.2(N2) U21.6(SCB1_1/GPIO_11)
CY_GPIO_12: R68.2(N2) U21.7(SCB1_2/GPIO_12)
CY_GPIO_13: R67.2(N2) U21.8(SCB1_3/GPIO_13)
CY_GPIO_16: TP25.1(P1) U21.13(GPIO_16)
CY_GPIO_18: TP28.1(P1) U21.22(GPIO_18)
DATEN: R45.1(N1) ; also on sheet 7
DE_T: R45.2(N2) U14.8(DE)
DEVA_I2C_SCL: R78.2(N2) R87.1(N1) U20.8(B1)
DEVA_I2C_SDA: R81.2(N2) R88.1(N1) U20.1(B2)
DEVA_I2COE: R79.1(N1) R80.1(N1) U20.6(OE)
DEVA_P3P3V: J13.4 R86.1(N1)
DEVA_SCL: J13.2 R87.2(N2) U29.6(IO2)
DEVA_SDA: J13.1 R88.2(N2) U29.3(IO1)
EDID_WEZ: J6.1 R101.1(N1) U11.7(WC/)
ENVBUS#: Q1.1(G) R27.1(N1) TP20.1(P1) U14.11(ENVBUS#) U19.4(\\~{E}N)
ENVBUS_SCL: Q1.2(S) R39.2(N2) R99.1(N1) U11.6(SCL)
EXT_IIC0_SCL: U14.14(PCSCL) ; also on sheet 6
EXT_IIC0_SDA: U14.13(PCSDA) ; also on sheet 6
GPIO_0_LED: D10.2(P2) R89.2(N2)
GPIO_0_LED_DRV: D10.1(P1) U30.4(Y)
GPIO_1_LED: D9.2(P2) R82.2(N2)
GPIO_1_LED_DRV: D9.1(P1) U23.4(Y)
HSYNC: R44.1(N1) ; also on sheet 7
HSYNC_T: R44.2(N2) U14.9(HSYNC)
IIC0_SCL: U18.5(A1) U20.5(A1) ; also on sheet 6 7
IIC0_SDA: U18.4(A2) U20.4(A2) ; also on sheet 6 7
IT6801_INTZ: R25.1(N1) R42.1(N1) ; also on sheet 6
IT_3DR: R64.1(N1) U14.44(I2S1_3DR)
IT_APVDD12: C26.1 C77.1(P) FB1.2 U14.37(APVDD12)
IT_AVCC12: C21.1 C62.1(P) FB2.2 U14.22(AVCC12)
IT_AVCC33: C28.1 C63.1(P) C75.1(P) C76.1(P) FB5.2 U14.25(AVCC33) U14.30(AVCC33) U14.35(AVCC33) U14.40(APVCC33)
IT_PCADR: R106.2(N2) R107.1(N1) U14.49(PCADR)
IT_PVCC12: C22.1 C64.1(P) FB3.2 U14.23(PVCC12)
IT_PVCC33: C23.1 C61.1(P) FB4.2 U14.24(PVCC33)
IT_R0PWR5V: R38.1(N1) R100.2(N2) U14.18(R0PWR5V)
IT_SYSRSTN: C32.1 R108.2(N2) R109.1(N1) U14.47(SYSRSTN)
IT_XTALIN: C79.1(P) R105.2(N2) U14.39(XTALIN) X1.3
IT_XTALOUT: C78.1(P) R105.1(N1) U14.38(XTALOUT) X1.1
ITE_CBUS_HPD: R37.1(N1) U14.21(CBUS/HPD)
ITE_DDCSCL0: R39.1(N1) U14.17(DDCSCL0)
ITE_DDCSDA0: R40.1(N1) U14.16(DDCSDA0)
ITE_INT#_CEC: R41.1(N1) R42.2(N2) U14.12(INT#_CEC)
LEDON3P3V: D7.2(P2) R7.2(N2)
LEDON5V: D1.2(P2) R2.2(N2)
mHOST_IRQ_B: U21.10(SCB1_5/GPIO_15) ; also on sheet 6 7
MSP430_ACK: R33.1(N1) U3.2(A) ; also on sheet 6
MSP430_ACK_LED: D3.2(P2) R18.2(N2)
MSP430_ACK_LED_DRV: D3.1(P1) U3.4(Y)
MSP430_PWREN: R4.1(N1) ; also on sheet 6
MSP430_REQ: R50.1(N1) U4.2(A) ; also on sheet 6
MSP430_REQ_LED: D4.2(P2) R19.2(N2)
MSP430_REQ_LED_DRV: D4.1(P1) U4.4(Y)
MSP_2IT_RSTN: R108.1(N1) ; also on sheet 6
mSPI0_CLK: R22.1(N1) ; also on sheet 7
mSPI0_CSZ0: R21.1(N1) ; also on sheet 7
mSPI0_MISO: U5.13(B2) ; also on sheet 7
mSPI0_MOSI: R23.1(N1) ; also on sheet 7
mSPI_CLK_T: R22.2(N2) U5.12(B3)
mSPI_CSZ0_T: R21.2(N2) U5.11(B4)
mSPI_MOSI_T: R23.2(N2) U5.14(B1)
P1P2V: C19.1(P) C24.1 C25.1(P) C57.1(P) C59.1(P) C60.1(P) C68.1(P) C72.1(P) C73.1(P) C74.1(P) C86.1(P) FB1.1 FB2.1 FB3.1 L3.2 R29.2(N2) TP12.1(P1) U14.7(IVDD12) U14.15(IVDD12) U14.36(DVDD12) U14.43(IVDD12) U14.48(IVDD12) U14.64(IVDD12) U14.71(IVDD12)
P1P2V_EN: R30.1(N1) U8.3(EN)
P1P2V_FB: C19.2(N) R28.1(N1) R29.1(N1) U8.4(FB)
P1P2V_SW: L3.1 U8.5(SW)
P1P8V_EN: R57.1(N1) U15.3(EN)
P1P8V_FB: C29.2(N) R55.1(N1) R56.2(N2) U15.5(FB)
P1P8V_NR: C30.1(P) U15.4(NR)
P1P8V_SB: C29.1(P) C33.1(P) C55.1(P) C82.1(P) C91.1(P) R56.1(N1) TP19.1(P1) U12.15(VCCB) U15.6(OUT) U18.3(VCCA) U20.3(VCCA) ; also on sheet 6 7
P3P3V_BT: C7.1(P) U1.1(BOOT)
P3P3V_COMP: C12.2(N) R11.2(N2) U1.6(COMP)
P3P3V_FB: R9.2(N2) R10.1(N1) U1.5(FB)
P3P3V_PWREN: R12.2(N2) R13.1(N1) U1.7(EN)
P3P3V_RC1: C13.2(N) R11.1(N1)
P3P3V_RT: R14.1(N1) U1.8(RT)
P3P3V_SB: C20.2(N) C27.1(P) C31.2(N) C45.1(P) C46.1(P) C50.1(P) C51.1(P) C52.1(P) C56.1(P) C58.1(P) C65.1 C67.1(P) C69.1(P) C70.1(P) C71.1(P) C81.1(P) C87.1(P) C90.1(P) C92.1(P) FB4.1 FB5.1 J5.6 R7.1(N1) R8.1(N1) R18.1(N1) R19.1(N1) R25.2(N2) R30.2(N2) R57.2(N2) R70.2(N2) R72.2(N2) R78.1(N1) R79.2(N2) R81.1(N1) R82.1(N1) R86.2(N2) R89.1(N1) R95.2(N2) R96.2(N2) R97.2(N2) R107.2(N2) R109.2(N2) TP5.1(P1) U3.5(PWR) U4.5(PWR) U5.1(DIR1) U5.7(DIR3) U5.8(DIR4) U5.15(VCCB) U5.16(VCCA) U8.1(VIN) U9.1(DIR1) U9.7(DIR3) U9.8(DIR4) U9.15(VCCB) U9.16(VCCA) U12.1(DIR1) U12.7(DIR3) U12.8(DIR4) U12.16(VCCA) U14.6(OVDD) U14.20(OVDD33) U14.50(OVDD) U14.55(OVDD) U14.63(OVDD) U14.70(OVDD) U14.76(OVDD) U15.1(IN) U18.7(VCCB) U20.7(VCCB) U21.1(VDDD) U21.23(VDDD) U22.5(PWR) U23.5(PWR) U29.1(VCC) U30.5(PWR) ; also on sheet 6 7
P3P3V_SW: C7.2(N) L2.2 U1.3(PH)
P3P3VSB: C11.1(P) L2.1 R8.2(N2) R9.1(N1)
PCLK: R46.1(N1) ; also on sheet 7
PCLK_T: R46.2(N2) U14.75(PCLK)
PDATA0: RP1.4 ; also on sheet 7
PDATA1: RP1.3 ; also on sheet 7
PDATA2: RP1.2 ; also on sheet 7
PDATA3: RP1.1 ; also on sheet 7
PDATA4: RP2.4 ; also on sheet 7
PDATA5: RP2.3 ; also on sheet 7
PDATA6: RP2.2 ; also on sheet 7
PDATA7: RP2.1 ; also on sheet 7
PDATA8: RP3.4 ; also on sheet 7
PDATA9: RP3.3 ; also on sheet 7
PDATA10: RP3.2 ; also on sheet 7
PDATA11: RP3.1 ; also on sheet 7
PDATA12: RP4.4 ; also on sheet 7
PDATA13: RP4.3 ; also on sheet 7
PDATA14: RP4.2 ; also on sheet 7
PDATA15: RP4.1 ; also on sheet 7
PDATA16: RP5.4 ; also on sheet 7
PDATA17: RP5.3 ; also on sheet 7
PDATA18: RP5.2 ; also on sheet 7
PDATA19: RP5.1 ; also on sheet 7
PDATA20: RP6.4 ; also on sheet 7
PDATA21: RP6.3 ; also on sheet 7
PDATA22: RP6.2 ; also on sheet 7
PDATA23: RP6.1 ; also on sheet 7
PDATA_T0: RP1.5 U14.5(QE4)
PDATA_T1: RP1.6 U14.4(QE5)
PDATA_T2: RP1.7 U14.3(QE6)
PDATA_T3: RP1.8 U14.2(QE7)
PDATA_T4: RP2.5 U14.1(QE8)
PDATA_T5: RP2.6 U14.74(QE9)
PDATA_T6: RP2.7 U14.73(QE10)
PDATA_T7: RP2.8 U14.72(QE11)
PDATA_T8: RP3.5 U14.69(QE16)
PDATA_T9: RP3.6 U14.68(QE17)
PDATA_T10: RP3.7 U14.67(QE18)
PDATA_T11: RP3.8 U14.66(QE19)
PDATA_T12: RP4.5 U14.65(QE20)
PDATA_T13: RP4.6 U14.62(QE21)
PDATA_T14: RP4.7 U14.61(QE22)
PDATA_T15: RP4.8 U14.60(QE23)
PDATA_T16: RP5.5 U14.59(QE28)
PDATA_T17: RP5.6 U14.58(QE29)
PDATA_T18: RP5.7 U14.57(QE30)
PDATA_T19: RP5.8 U14.56(QE31)
PDATA_T20: RP6.5 U14.54(QE32)
PDATA_T21: RP6.6 U14.53(QE33)
PDATA_T22: RP6.7 U14.52(QE34)
PDATA_T23: RP6.8 U14.51(QE35)
RX0_N: J11.9(DATA0-/MHL-) U14.28(P0_RX0N) U26.2(D1-) U26.9(NC)
RX0_P: J11.8(DATA0+/MHL+) U14.29(P0_RX0P) U26.1(D1+) U26.10(NC)
RX1_N: J11.6(DATA1-) U14.31(P0_RX1N) U27.5(D2-) U27.6(NC)
RX1_P: J11.5(DATA1+) U14.32(P0_RX1P) U27.4(D2+) U27.7(NC)
RX2_N: J11.3(DATA2-) U14.33(P0_RX2N) U27.2(D1-) U27.9(NC)
RX2_P: J11.2(DATA2+) U14.34(P0_RX2P) U27.1(D1+) U27.10(NC)
RX_I2S0: J5.1 R63.2(N2)
RX_I2S0_T: R63.1(N1) U14.42(I2S0)
RX_MCLK: J5.4 R62.2(N2)
RX_MCLK_T: R62.1(N1) U14.41(MUTE_MCLK)
RX_SCLK: J5.3 R66.2(N2)
RX_SCLK_T: R66.1(N1) U14.46(SCK_MCLK)
RX_WS: J5.2 R65.2(N2)
RX_WS_T: R65.1(N1) U14.45(WS_SPDIF)
RXCLK_N: J11.12(CLK-) U14.26(P0_RXCN) U26.5(D2-) U26.6(NC)
RXCLK_P: J11.11(CLK+) U14.27(P0_RXCP) U26.4(D2+) U26.7(NC)
sSPI0_CLK: R32.1(N1) ; also on sheet 7
sSPI0_CSZ0: R31.1(N1) ; also on sheet 7
sSPI0_MISO: U9.13(B2) ; also on sheet 7
sSPI0_MOSI: R47.1(N1) ; also on sheet 7
sSPI_CLK_T: R32.2(N2) U9.12(B3)
sSPI_CSZ0_T: R31.2(N2) U9.11(B4)
sSPI_MOSI_T: R47.2(N2) U9.14(B1)
SUSPEND: TP23.1(P1) U21.11(SUSPEND)
SW_ONOFF: U22.4(Y) ; also on sheet 6
USB_AUX_SPI_OEZ: R97.1(N1) U12.9(~{OE}) U21.21(GPIO_17) ; also on sheet 7
USB_IIC0_OE: R71.1(N1) U18.6(OE) U21.3(SCB0_5/GPIO_9)
USB_IIC0_SCL: R72.1(N1) U18.8(B1) U21.28(SCB0_2/GPIO_3)
USB_IIC0_SDA: R70.1(N1) U18.1(B2) U21.29(SCB0_3/GPIO_4)
USB_SPI_CLK: R67.1(N1) U5.5(A3) U9.5(A3) U12.5(A3)
USB_SPI_CSZ: R68.1(N1) U5.6(A4) U9.6(A4) U12.6(A4)
USB_SPI_M_OEZ: R95.1(N1) U5.9(~{OE}) U21.2(SCB0_0/GPIO_8)
USB_SPI_MISO: U5.4(A2) U9.4(A2) U12.4(A2) U21.5(SCB1_0/GPIO_10)
USB_SPI_MOSI: R69.1(N1) U5.3(A1) U9.3(A1) U12.3(A1)
USB_SPI_S_OEZ: R96.1(N1) TP22.1(P1) U9.9(~{OE}) U21.9(SCB1_4/GPIO_14)
USB_VBUS: C38.2(N) J12.1(VUSB) U21.19(VBUS)
USBDM: J12.2(D-) U21.15(USBDM) U28.3(IO1)
USBDP: J12.3(D+) U21.14(USBDP) U28.5(IO2)
VSENSE_P5V_VIN: R5.2(N2) R6.1(N1) U2.5(FB)
VSYNC: R43.1(N1) ; also on sheet 7
VSYNC_T: R43.2(N2) U14.10(VSYNC)
WAKEUP: TP24.1(P1) U21.12(WAKEUP)

Not connected (* = marked no-connect by the designer): J12 4(ID)*; U19 3(\\~{FL}T); U21 18(nXRES)*; U24 2(NC2)* 5(NC5)*; U25 2(NC2)* 5(NC5)*; U28 1(NC1)* 2(NC2)*; U29 2(NC2)* 5(NC5)*

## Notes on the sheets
sheet 2
- DLPC3434 SYSTEM BOARD
       REFERENCE DESIGN
sheet 3
- +19V
  Power
  Input
- 3A Output
- shield pins
- pin 2 -
  sleeve
- pin 1 - pin
- Vout=0.8V(1+R78/R80)
- FAN POWER
  CONNECTORS
- shield pins
- jack insert direction
- "Standby" power for frontend electronics and SPI Flash
- 2A Out
- Vout=0.8V(1+R122/R121)
- IT6801
  1.2V Core
- 200mA Out
- FB=0.6V
- 600mA Out
- BOARD MOUNTING HOLES
- 19V INPUT & POWER SUPPLIES
sheet 4
- 1
- 3
- 2
- Do Not
  Install
- Do Not
  Install
- Provide power to source per MHL spec
  Load switch limit to 1A draw
- Do Not
  Install
- I2S or
  S/PDIF
- Set IT6801's OVDD to 3.3V
- HDMI & IT6801
sheet 5
- DEVASYS
  CONNECTOR
- SCB0 configured as I2C Master (Mode 5)
  SCB1 configured as SPI Master (Mode 3)
- EXTERNAL I2C & USB CONNECTIONS
